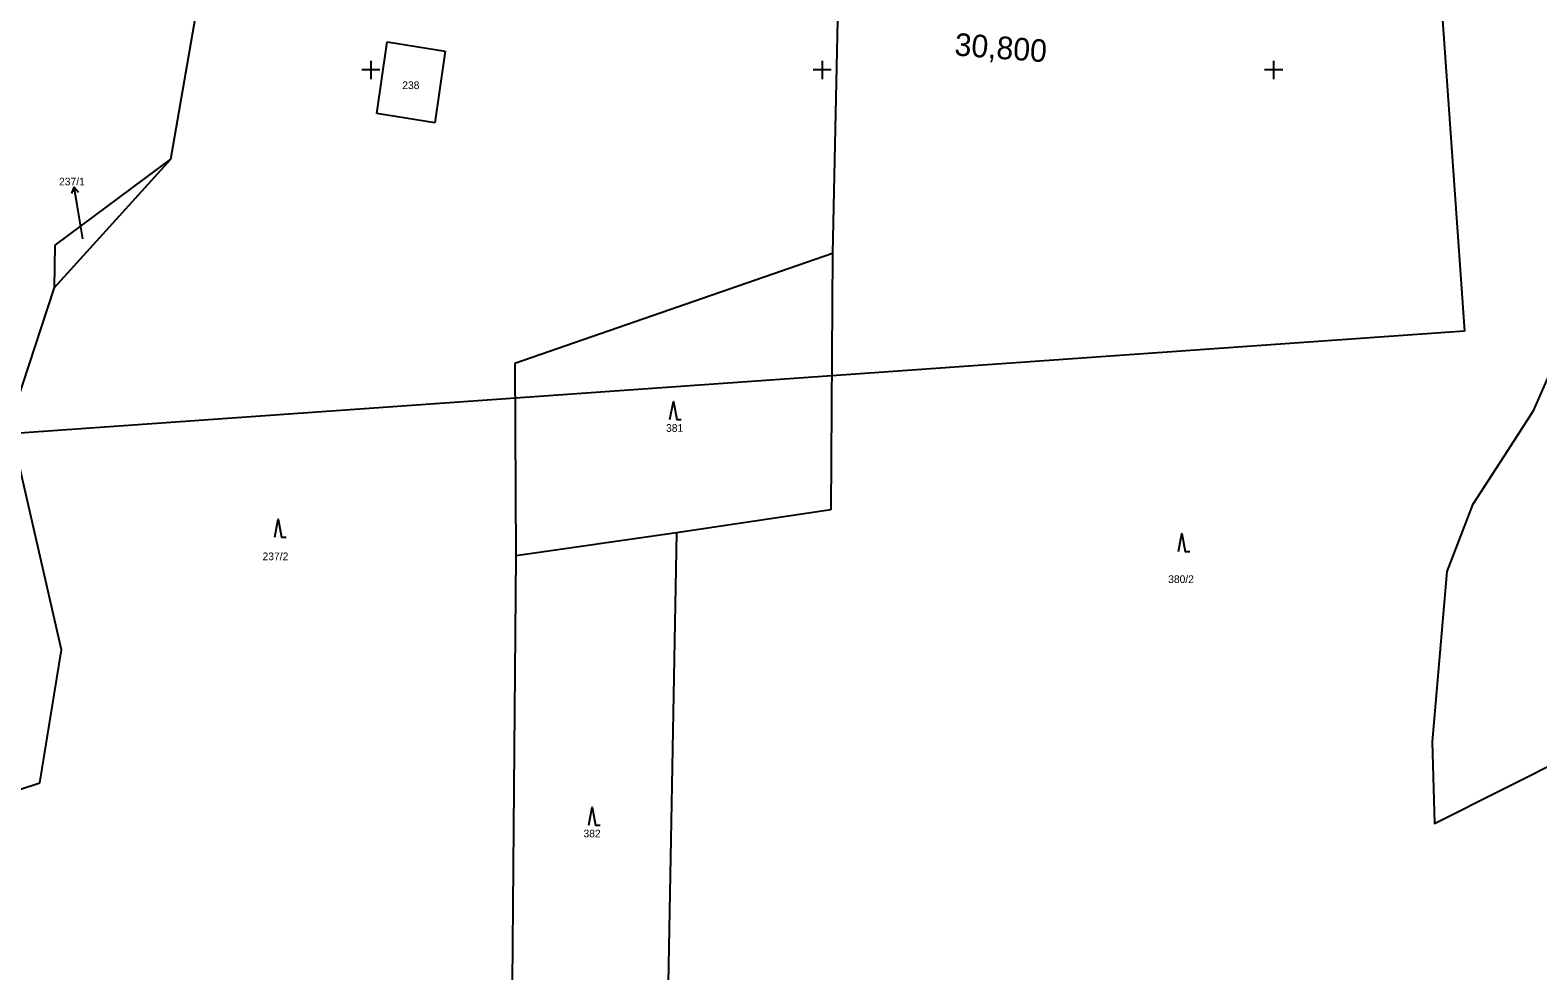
# Model space of a CAD drawing. Extents: x -670359 to -668019, y -978807 to -976674.
# Drawn here: x -669575.5 to -669241.5, y -977399.4 to -977191.2 of the extents above; entities that cross this region are included whole.
import ezdxf

# ---------------------------------------------------------------- set-up
doc = ezdxf.new("R2010")
doc.units = 0
for name, color, linetype in [('Hranice parcel', 7, 'Continuous'), ('Parcelní čísla', 7, 'Continuous'), ('SO 11-10-01', 7, 'Continuous'), ('Značky kultur', 7, 'Continuous'), ('čtvercová síť', 7, 'Continuous')]:
    doc.layers.add(name, color=color, linetype=linetype)

msp = doc.modelspace()

# ---------------------------------------------------------------- linework, layer by layer
at = {"layer": 'Defpoints'}
for p, q in [((-669278.09, -976969.54), (-669257.73, -977257.82)), ((-669257.73, -977257.82), (-669676.69, -977287.4))]:
    msp.add_line(p, q, dxfattribs=at)
at = {"layer": 'Hranice parcel'}
for points in [[(-669396.17, -977168.17), (-669397.7, -977240.66)], [(-669544.29, -977219.72), (-669537.96, -977183.16)], [(-669498.71, -977209.62), (-669496.38, -977193.76)], [(-669496.38, -977193.76), (-669483.51, -977195.84)], [(-669229.74, -977193.65), (-669233.63, -977255.3), (-669242.61, -977275.64), (-669249.01, -977285.54), (-669255.96, -977296.28), (-669261.61, -977311.07), (-669264.91, -977348.74), (-669264.35, -977366.82), (-669233.76, -977351.5), (-669205.54, -977355.99)], [(-669483.51, -977195.84), (-669485.84, -977211.7)], [(-669485.84, -977211.7), (-669498.71, -977209.62)], [(-669570.08, -977248.16), (-669544.29, -977219.72)], [(-669569.97, -977238.81), (-669544.29, -977219.72)], [(-669570.08, -977248.16), (-669569.97, -977238.81)], [(-669397.7, -977240.66), (-669468.1, -977264.98)], [(-669397.7, -977240.66), (-669398.11, -977297.4)], [(-669579.99, -977278.35), (-669570.08, -977248.16)], [(-669468.1, -977264.98), (-669467.87, -977307.57)], [(-669568.52, -977328.39), (-669579.99, -977278.35)], [(-669398.11, -977297.4), (-669432.31, -977302.48)], [(-669432.31, -977302.48), (-669467.87, -977307.57)], [(-669432.31, -977302.48), (-669434.41, -977418.21)], [(-669467.87, -977307.57), (-669469.02, -977436.56)], [(-669573.32, -977357.82), (-669568.52, -977328.39)], [(-669592.8, -977364.17), (-669573.32, -977357.82)]]:
    msp.add_lwpolyline(points, dxfattribs=at)
at = {"layer": 'Parcelní čísla'}
for p, q in [((-669566.27, -977227.33), (-669565.75, -977225.92)), ((-669563.84, -977237.41), (-669565.09, -977229.87))]:
    msp.add_line(p, q, dxfattribs=at)
msp.add_lwpolyline([(-669565.09, -977229.87), (-669565.75, -977225.92), (-669564.79, -977227.08)], dxfattribs=at)
at = {"layer": 'Značky kultur'}
for points in [[(-669433.74, -977277.41), (-669432.99, -977273.41), (-669432.24, -977277.41), (-669431.24, -977277.41)], [(-669521.3, -977303.45), (-669520.55, -977299.45), (-669519.8, -977303.45), (-669518.8, -977303.45)], [(-669321.08, -977306.61), (-669320.33, -977302.61), (-669319.58, -977306.61), (-669318.58, -977306.61)], [(-669451.72, -977367.19), (-669450.97, -977363.19), (-669450.22, -977367.19), (-669449.22, -977367.19)]]:
    msp.add_lwpolyline(points, dxfattribs=at)
at = {"layer": 'čtvercová síť'}
for p, q in [((-669500, -977198), (-669500, -977202)), ((-669400, -977198), (-669400, -977202)), ((-669300, -977198), (-669300, -977202)), ((-669498, -977200), (-669502, -977200)), ((-669498, -977200), (-669502, -977200)), ((-669398, -977200), (-669402, -977200)), ((-669398, -977200), (-669402, -977200)), ((-669298, -977200), (-669302, -977200)), ((-669298, -977200), (-669302, -977200))]:
    msp.add_line(p, q, dxfattribs=at)

# ---------------------------------------------------------------- texts
at = {"layer": 'Parcelní čísla'}
for s, height, p in [('238', 1.7, (-669493.04, -977204.23)), ('237/1', 1.7, (-669569.08, -977225.55)), ('237/1', 0.1, (-669564.02, -977237.41)), ('381', 1.7, (-669434.6, -977280.11)), ('237/2', 1.7, (-669524, -977308.53)), ('380/2', 1.7, (-669323.36, -977313.58)), ('382', 1.7, (-669452.9, -977369.89))]:
    msp.add_text(s, height=height, dxfattribs=at).set_placement(p)
at = {"layer": 'SO 11-10-01'}
msp.add_text('30,800', height=5, rotation=355.6391, dxfattribs=at).set_placement((-669370.82, -977196.77))

doc.saveas('drawing.dxf')
